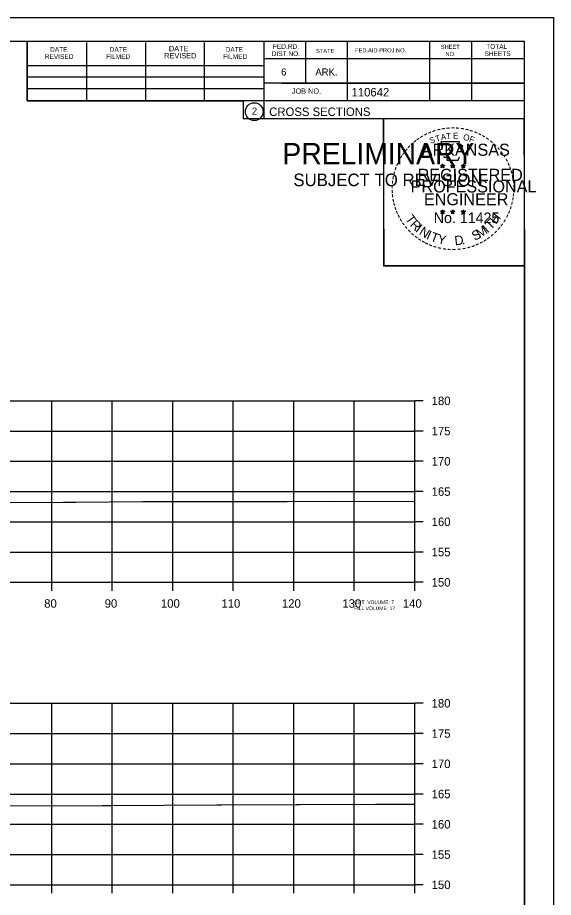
# Model space of a CAD drawing. Extents: x 1368503 to 1373085, y 379840 to 381833.
# Drawn here: x 1368747.4 to 1368836, y 379980.6 to 380126 of the extents above; entities that cross this region are included whole.
import ezdxf

# ---------------------------------------------------------------- set-up
doc = ezdxf.new("R2010")
doc.units = 0
for name, color, linetype in [('S_BRIDGE', 7, 'Continuous'), ('S_EDGE_PAVEMENT', 7, 'Continuous'), ('S_LANDSCAPING', 7, 'Continuous'), ('S_MISC_BOUNDARY', 7, 'Continuous'), ('S_MISC_BOUNDARY_ANNOT', 7, 'Continuous'), ('S_PHOTO_CENTERS', 7, 'Continuous'), ('S_PHOTO_NOTES', 7, 'Continuous'), ('S_TRAILS', 7, 'Continuous')]:
    doc.layers.add(name, color=color, linetype=linetype)

msp = doc.modelspace()

# ---------------------------------------------------------------- linework, layer by layer
at = {"layer": 'S_BRIDGE'}
for p, q in [((1368515.06, 380122.15), (1368831.24, 380122.15)), ((1368748.98, 380112.27), (1368748.98, 380122.15)), ((1368758.84, 380112.27), (1368758.84, 380121.95)), ((1368768.6, 380112.27), (1368768.6, 380121.95)), ((1368778.28, 380112.27), (1368778.28, 380121.95)), ((1368788.14, 380122.15), (1368788.14, 380109.35)), ((1368794.98, 380122.15), (1368794.98, 380115.21)), ((1368801.92, 380122.15), (1368801.92, 380112.27)), ((1368815.5, 380122.15), (1368815.5, 380112.27)), ((1368822.44, 380122.15), (1368822.44, 380112.27)), ((1368831.24, 379916.69), (1368831.24, 380122.15)), ((1368831.24, 380119.21), (1368788.14, 380119.21)), ((1368831.24, 380119.23), (1368831.24, 380119.23)), ((1368748.98, 380118.13), (1368788.14, 380118.13)), ((1368748.98, 380116.27), (1368788.14, 380116.27)), ((1368748.98, 380112.27), (1368748.98, 380114.33)), ((1368748.98, 380114.33), (1368788.14, 380114.33)), ((1368831.24, 380115.21), (1368788.14, 380115.21)), ((1368791.1, 380115.21), (1368831.24, 380115.21)), ((1368831.24, 380112.27), (1368748.98, 380112.27)), ((1368788.14, 380109.35), (1368831.24, 380109.35))]:
    msp.add_line(p, q, dxfattribs=at)
msp.add_circle((1368786.53, 380110.49), 1.47, dxfattribs=at)
at = {"layer": 'S_EDGE_PAVEMENT'}
for p, q in [((1368813.06, 380032.69), (1368813.06, 380062.69)), ((1368814.46, 380062.69), (1368813.06, 380062.69)), ((1368814.46, 380057.69), (1368813.06, 380057.69)), ((1368814.46, 380052.69), (1368813.06, 380052.69)), ((1368814.46, 380047.69), (1368813.06, 380047.69)), ((1368814.46, 380042.69), (1368813.06, 380042.69)), ((1368814.46, 380037.69), (1368813.06, 380037.69)), ((1368533.06, 380032.69), (1368813.06, 380032.69)), ((1368753.06, 380031.29), (1368753.06, 380032.69)), ((1368763.06, 380031.29), (1368763.06, 380032.69)), ((1368773.06, 380031.29), (1368773.06, 380032.69)), ((1368783.06, 380031.29), (1368783.06, 380032.69)), ((1368793.06, 380031.29), (1368793.06, 380032.69)), ((1368803.06, 380031.29), (1368803.06, 380032.69)), ((1368813.06, 380031.29), (1368813.06, 380032.69)), ((1368814.46, 380032.69), (1368813.06, 380032.69)), ((1368813.06, 379982.69), (1368813.06, 380012.69)), ((1368814.46, 380012.69), (1368813.06, 380012.69)), ((1368814.46, 380007.69), (1368813.06, 380007.69)), ((1368814.46, 380002.69), (1368813.06, 380002.69)), ((1368814.46, 379997.69), (1368813.06, 379997.69)), ((1368814.46, 379992.69), (1368813.06, 379992.69)), ((1368814.46, 379987.69), (1368813.06, 379987.69)), ((1368533.06, 379982.69), (1368813.06, 379982.69)), ((1368753.06, 379981.29), (1368753.06, 379982.69)), ((1368763.06, 379981.29), (1368763.06, 379982.69)), ((1368773.06, 379981.29), (1368773.06, 379982.69)), ((1368783.06, 379981.29), (1368783.06, 379982.69)), ((1368793.06, 379981.29), (1368793.06, 379982.69)), ((1368803.06, 379981.29), (1368803.06, 379982.69)), ((1368813.06, 379981.29), (1368813.06, 379982.69)), ((1368814.46, 379982.69), (1368813.06, 379982.69))]:
    msp.add_line(p, q, dxfattribs=at)
at = {"layer": 'S_LANDSCAPING'}
for p, q in [((1368817.32, 380101.61), (1368817.67, 380101.49)), ((1368817.32, 380101.61), (1368817.58, 380101.56)), ((1368817.32, 380101.61), (1368817.56, 380101.48)), ((1368817.46, 380101.2), (1368817.67, 380101.49)), ((1368817.46, 380101.2), (1368817.58, 380101.44)), ((1368817.46, 380101.2), (1368817.67, 380101.41)), ((1368817.67, 380101.86), (1368817.63, 380101.61)), ((1368817.67, 380101.49), (1368817.67, 380101.86)), ((1368817.67, 380101.86), (1368817.72, 380101.61)), ((1368818.02, 380101.61), (1368817.67, 380101.49)), ((1368817.89, 380101.2), (1368817.67, 380101.49)), ((1368817.89, 380101.2), (1368817.67, 380101.41)), ((1368818.02, 380101.61), (1368817.73, 380101.56)), ((1368817.89, 380101.2), (1368817.75, 380101.49)), ((1368818.02, 380101.61), (1368817.82, 380101.5)), ((1368818.99, 380101.61), (1368819.34, 380101.49)), ((1368818.99, 380101.61), (1368819.25, 380101.56)), ((1368818.99, 380101.61), (1368819.23, 380101.48)), ((1368819.13, 380101.2), (1368819.34, 380101.49)), ((1368819.13, 380101.2), (1368819.25, 380101.44)), ((1368819.13, 380101.2), (1368819.34, 380101.41)), ((1368819.34, 380101.86), (1368819.3, 380101.61)), ((1368819.34, 380101.49), (1368819.34, 380101.86)), ((1368819.34, 380101.86), (1368819.39, 380101.61)), ((1368819.69, 380101.61), (1368819.34, 380101.49)), ((1368819.56, 380101.2), (1368819.34, 380101.49)), ((1368819.56, 380101.2), (1368819.34, 380101.41)), ((1368819.69, 380101.61), (1368819.4, 380101.56)), ((1368819.56, 380101.2), (1368819.42, 380101.49)), ((1368819.69, 380101.61), (1368819.49, 380101.5)), ((1368820.76, 380101.59), (1368821.11, 380101.48)), ((1368820.76, 380101.59), (1368821.01, 380101.55)), ((1368820.76, 380101.59), (1368820.99, 380101.47)), ((1368820.89, 380101.19), (1368821.11, 380101.48)), ((1368820.89, 380101.19), (1368821.02, 380101.43)), ((1368820.89, 380101.19), (1368821.1, 380101.4)), ((1368821.11, 380101.85), (1368821.07, 380101.6)), ((1368821.32, 380101.19), (1368821.1, 380101.4)), ((1368821.11, 380101.48), (1368821.11, 380101.85)), ((1368821.11, 380101.85), (1368821.16, 380101.6)), ((1368821.45, 380101.59), (1368821.11, 380101.48)), ((1368821.32, 380101.19), (1368821.11, 380101.48)), ((1368821.45, 380101.59), (1368821.17, 380101.54)), ((1368821.32, 380101.19), (1368821.18, 380101.48)), ((1368821.45, 380101.59), (1368821.25, 380101.49)), ((1368817.32, 380094.03), (1368817.67, 380093.92)), ((1368817.32, 380094.03), (1368817.57, 380093.99)), ((1368817.32, 380094.03), (1368817.56, 380093.91)), ((1368817.45, 380093.62), (1368817.67, 380093.92)), ((1368817.45, 380093.62), (1368817.58, 380093.87)), ((1368817.45, 380093.62), (1368817.67, 380093.84)), ((1368817.67, 380094.29), (1368817.63, 380094.03)), ((1368817.67, 380093.92), (1368817.67, 380094.29)), ((1368817.67, 380094.29), (1368817.72, 380094.04)), ((1368818.02, 380094.03), (1368817.67, 380093.92)), ((1368817.88, 380093.62), (1368817.67, 380093.92)), ((1368817.88, 380093.62), (1368817.67, 380093.84)), ((1368818.02, 380094.03), (1368817.73, 380093.98)), ((1368817.88, 380093.62), (1368817.74, 380093.92)), ((1368818.02, 380094.03), (1368817.81, 380093.93)), ((1368818.99, 380094.03), (1368819.34, 380093.92)), ((1368818.99, 380094.03), (1368819.24, 380093.99)), ((1368818.99, 380094.03), (1368819.23, 380093.91)), ((1368819.12, 380093.62), (1368819.34, 380093.92)), ((1368819.12, 380093.62), (1368819.25, 380093.87)), ((1368819.12, 380093.62), (1368819.34, 380093.84)), ((1368819.34, 380094.29), (1368819.3, 380094.03)), ((1368819.34, 380093.92), (1368819.34, 380094.29)), ((1368819.34, 380094.29), (1368819.39, 380094.04)), ((1368819.68, 380094.03), (1368819.34, 380093.92)), ((1368819.55, 380093.62), (1368819.34, 380093.92)), ((1368819.55, 380093.62), (1368819.34, 380093.84)), ((1368819.68, 380094.03), (1368819.4, 380093.98)), ((1368819.55, 380093.62), (1368819.41, 380093.92)), ((1368819.68, 380094.03), (1368819.48, 380093.93)), ((1368820.76, 380094.02), (1368821.1, 380093.91)), ((1368820.76, 380094.02), (1368821.01, 380093.98)), ((1368820.76, 380094.02), (1368820.99, 380093.9)), ((1368820.89, 380093.61), (1368821.1, 380093.91)), ((1368820.89, 380093.61), (1368821.01, 380093.86)), ((1368820.89, 380093.61), (1368821.1, 380093.83)), ((1368821.1, 380094.28), (1368821.06, 380094.02)), ((1368821.1, 380093.91), (1368821.1, 380094.28)), ((1368821.1, 380094.28), (1368821.15, 380094.03)), ((1368821.45, 380094.02), (1368821.1, 380093.91)), ((1368821.32, 380093.61), (1368821.1, 380093.91)), ((1368821.32, 380093.61), (1368821.1, 380093.83)), ((1368821.45, 380094.02), (1368821.17, 380093.97)), ((1368821.32, 380093.61), (1368821.18, 380093.91)), ((1368821.45, 380094.02), (1368821.25, 380093.92))]:
    msp.add_line(p, q, dxfattribs=at)
for points in [[(1368817.36, 380105.48), (1368817.63, 380104.66)], [(1368820.88, 380104.56), (1368821.02, 380104.85), (1368820.33, 380104.82), (1368820.48, 380105.48), (1368817.36, 380105.48)], [(1368817.86, 380103.06), (1368817.86, 380102.97), (1368818.42, 380102.95), (1368818.37, 380102.48), (1368820.24, 380102.48), (1368820.44, 380103.02)], [(1368817.67, 380101.86), (1368817.89, 380101.2), (1368817.32, 380101.61), (1368818.02, 380101.61), (1368817.46, 380101.2), (1368817.67, 380101.86)], [(1368819.34, 380101.86), (1368819.56, 380101.2), (1368818.99, 380101.61), (1368819.69, 380101.61), (1368819.13, 380101.2), (1368819.34, 380101.86)], [(1368821.11, 380101.85), (1368821.32, 380101.19), (1368820.76, 380101.59), (1368821.45, 380101.59), (1368820.89, 380101.19), (1368821.11, 380101.85)], [(1368817.67, 380094.29), (1368817.88, 380093.62), (1368817.32, 380094.03), (1368818.02, 380094.03), (1368817.45, 380093.62), (1368817.67, 380094.29)], [(1368819.34, 380094.29), (1368819.55, 380093.62), (1368818.99, 380094.03), (1368819.68, 380094.03), (1368819.12, 380093.62), (1368819.34, 380094.29)], [(1368821.1, 380094.28), (1368821.32, 380093.61), (1368820.76, 380094.02), (1368821.45, 380094.02), (1368820.89, 380093.61), (1368821.1, 380094.28)]]:
    msp.add_lwpolyline(points, dxfattribs=at)
for centre, radius in [((1368817.67, 380101.49), 0.172), ((1368817.67, 380101.49), 0.145), ((1368817.67, 380101.49), 0.116), ((1368817.67, 380101.49), 0.0991), ((1368817.67, 380101.49), 0.0747), ((1368817.67, 380101.49), 0.0495), ((1368817.67, 380101.49), 0.0296), ((1368819.34, 380101.49), 0.172), ((1368819.34, 380101.49), 0.145), ((1368819.34, 380101.49), 0.116), ((1368819.34, 380101.49), 0.0991), ((1368819.34, 380101.49), 0.0747), ((1368819.34, 380101.49), 0.0495), ((1368819.34, 380101.49), 0.0296), ((1368821.11, 380101.48), 0.172), ((1368821.11, 380101.48), 0.145), ((1368821.11, 380101.48), 0.116), ((1368821.11, 380101.48), 0.0991), ((1368821.11, 380101.48), 0.0747), ((1368821.11, 380101.48), 0.0495), ((1368821.11, 380101.48), 0.0296), ((1368817.67, 380093.92), 0.172), ((1368817.67, 380093.92), 0.145), ((1368817.67, 380093.92), 0.116), ((1368817.67, 380093.92), 0.0991), ((1368817.67, 380093.92), 0.0747), ((1368817.67, 380093.92), 0.0495), ((1368817.67, 380093.92), 0.0296), ((1368819.34, 380093.92), 0.172), ((1368819.34, 380093.92), 0.145), ((1368819.34, 380093.92), 0.116), ((1368819.34, 380093.92), 0.0991), ((1368819.34, 380093.92), 0.0747), ((1368819.34, 380093.92), 0.0495), ((1368819.34, 380093.92), 0.0296), ((1368821.1, 380093.91), 0.172), ((1368821.1, 380093.91), 0.145), ((1368821.1, 380093.91), 0.116), ((1368821.1, 380093.91), 0.0991), ((1368821.1, 380093.91), 0.0747), ((1368821.1, 380093.91), 0.0495), ((1368821.1, 380093.91), 0.0296)]:
    msp.add_circle(centre, radius, dxfattribs=at)
at = {"layer": 'S_MISC_BOUNDARY'}
for points in [[(1368742.32, 380045.88), (1368754.95, 380045.93), (1368757.04, 380045.93), (1368768.12, 380046.03), (1368769.89, 380046.03), (1368783.91, 380046.04), (1368791.97, 380046.06), (1368799.46, 380046.12), (1368813.06, 380046.03)], [(1368742.58, 379995.75), (1368761.43, 379995.79), (1368762.8, 379995.8), (1368780.33, 379995.91), (1368781.09, 379995.91), (1368793.45, 379995.96), (1368794.12, 379995.96), (1368806.56, 379996.01), (1368807.55, 379996), (1368813.06, 379995.99)]]:
    msp.add_lwpolyline(points, dxfattribs=at)
at = {"layer": 'S_PHOTO_CENTERS'}
for p, q in [((1368533.06, 380062.69), (1368813.06, 380062.69)), ((1368753.06, 380032.69), (1368753.06, 380062.69)), ((1368763.06, 380032.69), (1368763.06, 380062.69)), ((1368773.06, 380032.69), (1368773.06, 380062.69)), ((1368783.06, 380032.69), (1368783.06, 380062.69)), ((1368793.06, 380032.69), (1368793.06, 380062.69)), ((1368803.06, 380032.69), (1368803.06, 380062.69)), ((1368813.06, 380032.69), (1368813.06, 380062.69)), ((1368533.06, 380057.69), (1368813.06, 380057.69)), ((1368533.06, 380052.69), (1368813.06, 380052.69)), ((1368533.06, 380047.69), (1368813.06, 380047.69)), ((1368533.06, 380042.69), (1368813.06, 380042.69)), ((1368533.06, 380037.69), (1368813.06, 380037.69)), ((1368533.06, 380032.69), (1368813.06, 380032.69)), ((1368533.06, 380012.69), (1368813.06, 380012.69)), ((1368753.06, 379982.69), (1368753.06, 380012.69)), ((1368763.06, 379982.69), (1368763.06, 380012.69)), ((1368773.06, 379982.69), (1368773.06, 380012.69)), ((1368783.06, 379982.69), (1368783.06, 380012.69)), ((1368793.06, 379982.69), (1368793.06, 380012.69)), ((1368803.06, 379982.69), (1368803.06, 380012.69)), ((1368813.06, 379982.69), (1368813.06, 380012.69)), ((1368533.06, 380007.69), (1368813.06, 380007.69)), ((1368533.06, 380002.69), (1368813.06, 380002.69)), ((1368533.06, 379997.69), (1368813.06, 379997.69)), ((1368533.06, 379992.69), (1368813.06, 379992.69)), ((1368533.06, 379987.69), (1368813.06, 379987.69)), ((1368533.06, 379982.69), (1368813.06, 379982.69))]:
    msp.add_line(p, q, dxfattribs=at)
at = {"layer": 'S_PHOTO_NOTES'}
for p, q in [((1368502.66, 380126.04), (1368835.99, 380126.04)), ((1368807.27, 380086.89), (1368807.27, 380086.89))]:
    msp.add_line(p, q, dxfattribs=at)
for points in [[(1368502.65, 380126.04), (1368835.99, 380126.04), (1368835.99, 379912.71), (1368502.65, 379912.71)], [(1368748.98, 380122.15), (1368748.98, 380112.27), (1368784.71, 380112.27), (1368784.71, 380109.35), (1368807.91, 380109.35), (1368807.91, 380085.02), (1368831.24, 380085.02), (1368831.24, 379916.69), (1368515.06, 379916.69), (1368515.06, 380122.15)], [(1368807.91, 380109.35), (1368831.12, 380109.35), (1368831.24, 380085.02), (1368808.03, 380085.02)]]:
    msp.add_lwpolyline(points, close=True, dxfattribs=at)

# ---------------------------------------------------------------- texts
at = {"layer": 'S_BRIDGE'}
for s, height, p in [('FED.RD.', 0.782, (1368789.62, 380120.87)), ('SHEET', 0.684, (1368817.36, 380120.87)), ('TOTAL', 0.782, (1368824.88, 380120.87)), ('REVISED', 0.782, (1368751.9, 380119.21)), ('DATE', 0.782, (1368752.78, 380120.39)), ('FILMED', 0.782, (1368762.06, 380119.21)), ('DATE', 0.782, (1368762.64, 380120.39)), ('REVISED', 0.879, (1368771.64, 380119.31)), ('DATE', 0.879, (1368772.42, 380120.49)), ('FILMED', 0.782, (1368781.4, 380119.21)), ('DATE', 0.782, (1368781.8, 380120.39)), ('DIST.NO.', 0.782, (1368789.42, 380119.69)), ('STATE', 0.684, (1368796.74, 380120.19)), ('FED.AID PROJ.NO.', 0.684, (1368803.2, 380120.29)), ('NO.', 0.684, (1368818.14, 380119.69)), ('SHEETS', 0.782, (1368824.6, 380119.69)), ('6', 1.17, (1368790.98, 380116.47)), ('ARK.', 1.172, (1368796.64, 380116.47)), ('JOB NO.', 0.879, (1368792.74, 380113.45)), ('110642', 1.4, (1368802.61, 380113.01)), ('2', 1.17, (1368786.14, 380110)), ('CROSS SECTIONS', 1.4, (1368789, 380109.78))]:
    msp.add_text(s, height=height, rotation=360, dxfattribs=at).set_placement(p)
at = {"layer": 'S_LANDSCAPING'}
for s, height, rotation, p in [('-', 1.6, 28.7918, (1368814.85, 380106.02)), ('-', 1.6, 24.3072, (1368815.48, 380106.34)), ('-', 1.6, 19.1761, (1368816.11, 380106.61)), ('-', 1.6, 13.6301, (1368816.86, 380106.85)), ('-', 1.6, 10.2193, (1368817.54, 380107.01)), ('T', 1, 6.0228, (1368818.31, 380105.91)), ('-', 1.6, 5.8968, (1368818.27, 380107.12)), ('-', 1.6, 0.1862, (1368819.04, 380107.2)), ('E', 1, 0.8323, (1368819.41, 380106.02)), ('-', 1.6, 357.743, (1368819.76, 380107.18)), ('-', 1.6, 352.1617, (1368820.51, 380107.13)), ('-', 1.6, 347.2049, (1368821.23, 380107.01)), ('-', 1.6, 342.3362, (1368821.86, 380106.86)), ('-', 1.6, 337.8551, (1368822.6, 380106.63)), ('-', 1.6, 334.1211, (1368823.23, 380106.36)), ('-', 1.6, 42.9622, (1368812.76, 380104.46)), ('-', 1.6, 38.9507, (1368813.19, 380104.88)), ('-', 1.6, 36.2317, (1368813.67, 380105.26)), ('-', 1.6, 34.0636, (1368814.25, 380105.65)), ('S', 1, 21.594, (1368815.72, 380105.16)), ('T', 1, 16.4036, (1368816.63, 380105.49)), ('A', 1, 11.2132, (1368817.46, 380105.74)), ('O', 1, 350.4515, (1368821.02, 380105.81)), ('F', 1, 340.0707, (1368821.97, 380105.58)), ('-', 1.6, 329.6409, (1368823.81, 380106.08)), ('-', 1.6, 325.8627, (1368824.45, 380105.72)), ('-', 1.6, 320.5297, (1368825.06, 380105.29)), ('-', 1.6, 50.6142, (1368811.91, 380103.5)), ('-', 1.6, 48.423, (1368812.31, 380103.99)), ('ARKANSAS', 2, 360, (1368814.22, 380103.2)), ('-', 1.6, 315.5786, (1368825.66, 380104.81)), ('-', 1.6, 309.8797, (1368826.23, 380104.26)), ('-', 1.6, 306.6522, (1368826.75, 380103.65)), ('-', 1.6, 62.8713, (1368810.86, 380101.79)), ('-', 1.6, 58.0706, (1368811.17, 380102.41)), ('-', 1.6, 54.2325, (1368811.5, 380102.93)), ('-', 1.4, 303.6753, (1368827.24, 380103.09)), ('-', 1.6, 299.6684, (1368827.56, 380102.48)), ('-', 1.6, 72.3945, (1368810.38, 380100.55)), ('-', 1.6, 67.7743, (1368810.6, 380101.18)), ('REGISTERED', 2, 360, (1368813.54, 380099.05)), ('DWB', 0.01, 360, (1368817.66, 380101.49)), ('DWB', 0.01, 360, (1368819.33, 380101.49)), ('DWB', 0.01, 360, (1368821.09, 380101.48)), ('-', 1.6, 294.6628, (1368827.88, 380101.87)), ('-', 1.6, 290.5728, (1368828.14, 380101.29)), ('-', 1.6, 81.2013, (1368810.05, 380099.12)), ('-', 1.6, 75.461, (1368810.18, 380099.84)), ('-', 1.6, 285.1233, (1368828.37, 380100.71)), ('-', 1.6, 280.5493, (1368828.57, 380099.97)), ('-', 1.6, 89.0622, (1368809.95, 380097.73)), ('-', 1.6, 85.1863, (1368809.98, 380098.43)), ('PROFESSIONAL', 2, 360, (1368812.39, 380097.14)), ('-', 1.6, 276.5962, (1368828.74, 380099.2)), ('-', 1.6, 274.3301, (1368828.8, 380098.48)), ('-', 1.6, 94.1959, (1368809.99, 380097.01)), ('-', 1.6, 98.9479, (1368810.06, 380096.34)), ('ENGINEER', 2, 360, (1368814.58, 380095.02)), ('-', 1.6, 263.5172, (1368828.81, 380097.18)), ('-', 1.6, 269.9407, (1368828.83, 380097.85)), ('-', 1.6, 101.7149, (1368810.19, 380095.61)), ('-', 1.6, 105.4578, (1368810.36, 380095.01)), ('-', 1.6, 255.7626, (1368828.63, 380095.85)), ('-', 1.6, 260.9953, (1368828.74, 380096.53)), ('-', 1.6, 109.0874, (1368810.57, 380094.38)), ('-', 1.6, 114.0643, (1368810.82, 380093.79)), ('No. 11425', 1.757, 360, (1368816.21, 380092.07)), ('DWB', 0.01, 360, (1368817.66, 380093.92)), ('DWB', 0.01, 360, (1368819.33, 380093.92)), ('DWB', 0.01, 360, (1368821.09, 380093.91)), ('H', 1.54, 54.6088, (1368826.55, 380091.79)), ('-', 1.6, 247.8887, (1368828.23, 380094.45)), ('-', 1.6, 252.8681, (1368828.45, 380095.13)), ('-', 1.6, 115.7289, (1368811.13, 380093.17)), ('-', 1.6, 120.4471, (1368811.49, 380092.58)), ('T', 1.54, 306.0406, (1368811.43, 380092.76)), ('R', 1.54, 314.005, (1368812.19, 380091.71)), ('T', 1.54, 46.6444, (1368825.66, 380090.85)), ('-', 1.6, 239.0712, (1368827.57, 380093.07)), ('-', 1.6, 244.6197, (1368827.96, 380093.83)), ('-', 1.6, 125.8934, (1368811.89, 380092.02)), ('-', 1.6, 130.7181, (1368812.35, 380091.47)), ('-', 1.6, 134.2238, (1368812.87, 380090.92)), ('I', 1.54, 321.9694, (1368813.09, 380090.78)), ('N', 1.54, 326.5002, (1368813.66, 380090.31)), ('S', 1.54, 26.9312, (1368822.97, 380089.12)), ('M', 1.54, 32.6563, (1368823.81, 380089.53)), ('I', 1.54, 42.1136, (1368825.1, 380090.37)), ('-', 1.6, 225.7653, (1368826.26, 380091.29)), ('-', 1.6, 231.2538, (1368826.74, 380091.85)), ('-', 1.6, 233.8452, (1368827.17, 380092.42)), ('-', 1.6, 138.9338, (1368813.39, 380090.46)), ('-', 1.6, 144.6463, (1368813.95, 380090.05)), ('-', 1.6, 148.0898, (1368814.51, 380089.68)), ('I', 1.54, 335.3603, (1368814.87, 380089.52)), ('T', 1.54, 339.8912, (1368815.53, 380089.19)), ('Y', 1.54, 347.8556, (1368816.74, 380088.75)), ('D', 1.54, 6.3969, (1368819.73, 380088.39)), ('-', 1.6, 212.2491, (1368824.65, 380089.92)), ('-', 1.6, 215.7363, (1368825.19, 380090.31)), ('-', 1.6, 221.0851, (1368825.74, 380090.78)), ('-', 1.6, 151.5704, (1368815.09, 380089.36)), ('-', 1.6, 154.6002, (1368815.61, 380089.11)), ('-', 1.6, 158.5612, (1368816.24, 380088.86)), ('-', 1.6, 162.7983, (1368816.92, 380088.64)), ('-', 1.6, 167.5555, (1368817.64, 380088.48)), ('-', 1.6, 191.2858, (1368821.45, 380088.54)), ('.', 1.54, 13.7642, (1368820.92, 380088.52)), ('-', 1.6, 195.4743, (1368822.18, 380088.74)), ('-', 1.6, 200.7184, (1368822.85, 380088.98)), ('-', 1.6, 204.2516, (1368823.47, 380089.26)), ('-', 1.6, 207.3568, (1368824.1, 380089.58)), ('-', 1.6, 173.1155, (1368818.41, 380088.37)), ('-', 1.6, 176.5183, (1368819.16, 380088.32)), ('-', 1.6, 181.5918, (1368819.9, 380088.34)), ('-', 1.6, 185.8167, (1368820.71, 380088.41))]:
    msp.add_text(s, height=height, rotation=rotation, dxfattribs=at).set_placement(p)
at = {"layer": 'S_MISC_BOUNDARY_ANNOT'}
for s, height, p in [('PRELIMINARY', 3.5, (1368791.19, 380101.81)), ('DWB', 0.01, (1368791.94, 380103.66)), ('SUBJECT TO REVISION', 2.0751, (1368793, 380098.18))]:
    msp.add_text(s, height=height, rotation=360, dxfattribs=at).set_placement(p)
at = {"layer": 'S_TRAILS'}
for s, height, p in [('180', 1.4, (1368815.86, 380061.99)), ('175', 1.4, (1368815.86, 380056.99)), ('170', 1.4, (1368815.86, 380051.99)), ('165', 1.4, (1368815.86, 380046.99)), ('160', 1.4, (1368815.86, 380041.99)), ('155', 1.4, (1368815.86, 380036.99)), ('150', 1.4, (1368815.86, 380031.99)), ('80', 1.4, (1368751.8, 380028.49)), ('90', 1.4, (1368761.8, 380028.49)), ('100', 1.4, (1368771.1, 380028.49)), ('110', 1.4, (1368781.1, 380028.49)), ('120', 1.4, (1368791.1, 380028.49)), ('130', 1.4, (1368801.1, 380028.49)), ('140', 1.4, (1368811.1, 380028.49)), ('CUT  VOLUME: 7', 0.6, (1368803.06, 380029.09)), ('FILL VOLUME: 17', 0.6, (1368803.06, 380028.09)), ('180', 1.4, (1368815.86, 380011.99)), ('175', 1.4, (1368815.86, 380006.99)), ('170', 1.4, (1368815.86, 380001.99)), ('165', 1.4, (1368815.86, 379996.99)), ('160', 1.4, (1368815.86, 379991.99)), ('155', 1.4, (1368815.86, 379986.99)), ('150', 1.4, (1368815.86, 379981.99))]:
    msp.add_text(s, height=height, dxfattribs=at).set_placement(p)

doc.saveas('drawing.dxf')
